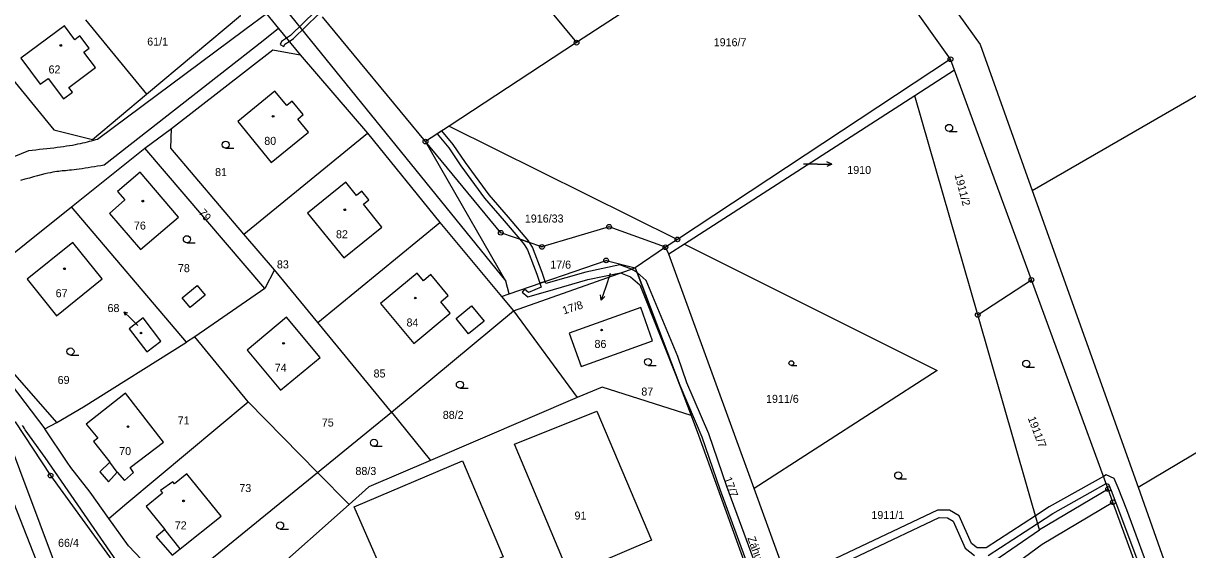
# Model space of a CAD drawing. Extents: x -504988 to -494607, y -1123820 to -1114018.
# Drawn here: x -497559.8 to -497312.5, y -1119487.8 to -1119375.9 of the extents above; entities that cross this region are included whole.
import ezdxf

# ---------------------------------------------------------------- set-up
doc = ezdxf.new("R2010")
doc.units = 0
for name, color, linetype in [('Hranice parcel', 7, 'Continuous'), ('Parcelní čísla', 7, 'Continuous'), ('Pop  PČ popisy', 7, 'Continuous'), ('Vnitřní kresba', 7, 'Continuous'), ('Věcná břemena k části', 7, 'Continuous'), ('Značky bodu BP', 7, 'Continuous'), ('Značky budov', 7, 'Continuous'), ('Značky kultur', 7, 'Continuous')]:
    doc.layers.add(name, color=color, linetype=linetype)

msp = doc.modelspace()

# ---------------------------------------------------------------- linework, layer by layer
at = {"layer": 'Hranice parcel'}
for p, q in [((-497362.83, -1119383.54), (-497389.7, -1119345.59)), ((-497466.94, -1119350.12), (-497442.25, -1119380.02)), ((-497413.46, -1119361.16), (-497442.25, -1119380.02)), ((-497546.51, -1119375.18), (-497533.57, -1119390.95)), ((-497474.33, -1119401.04), (-497496.22, -1119374.52)), ((-497442.25, -1119380.02), (-497469.31, -1119397.75)), ((-497500.92, -1119382.63), (-497486.64, -1119399.22)), ((-497362.83, -1119383.54), (-497420.84, -1119421.83)), ((-497361.97, -1119385.89), (-497362.83, -1119383.54)), ((-497361.97, -1119385.89), (-497370.38, -1119391.3)), ((-497345.64, -1119430.45), (-497361.97, -1119385.89)), ((-497370.38, -1119391.3), (-497419.32, -1119422.82)), ((-497357.03, -1119437.88), (-497370.38, -1119391.3)), ((-497533.91, -1119402.42), (-497528.28, -1119398.23)), ((-497469.31, -1119397.75), (-497474.33, -1119401.04)), ((-497469.31, -1119397.75), (-497420.84, -1119421.83)), ((-497512.89, -1119420.75), (-497486.64, -1119399.22)), ((-497486.64, -1119399.22), (-497471.31, -1119418.26)), ((-497549.48, -1119414.92), (-497533.91, -1119402.42)), ((-497508.44, -1119432.28), (-497533.91, -1119402.42)), ((-497345.47, -1119411.41), (-497322.99, -1119474.49)), ((-497525.07, -1119443.64), (-497549.48, -1119414.92)), ((-497497.21, -1119439.47), (-497471.31, -1119418.26)), ((-497471.31, -1119418.26), (-497458.19, -1119433.94)), ((-497506.41, -1119428.32), (-497512.89, -1119420.75)), ((-497420.84, -1119421.83), (-497423.37, -1119423.49)), ((-497419.32, -1119422.82), (-497422.68, -1119424.99)), ((-497423.37, -1119423.49), (-497429.79, -1119427.85)), ((-497422.68, -1119424.99), (-497423.37, -1119423.49)), ((-497404.54, -1119474.79), (-497422.68, -1119424.99)), ((-497506.41, -1119428.32), (-497508.44, -1119432.28)), ((-497497.21, -1119439.47), (-497506.41, -1119428.32)), ((-497455.62, -1119437.01), (-497429.79, -1119427.85)), ((-497429.79, -1119427.85), (-497417.89, -1119459.27)), ((-497357.03, -1119437.88), (-497345.64, -1119430.45)), ((-497329.36, -1119474.87), (-497345.64, -1119430.45)), ((-497508.44, -1119432.28), (-497523.31, -1119442.55)), ((-497458.19, -1119433.94), (-497456.56, -1119433.38)), ((-497458.19, -1119433.94), (-497455.62, -1119437.01)), ((-497481.58, -1119458.57), (-497455.62, -1119437.01)), ((-497455.62, -1119437.01), (-497442.09, -1119455.42)), ((-497343.95, -1119483.52), (-497357.03, -1119437.88)), ((-497481.58, -1119458.57), (-497497.21, -1119439.47)), ((-497523.31, -1119442.55), (-497525.07, -1119443.64)), ((-497511.96, -1119456.38), (-497523.31, -1119442.55)), ((-497442.09, -1119455.42), (-497473.29, -1119468.81)), ((-497497.24, -1119471.33), (-497511.96, -1119456.38)), ((-497550.62, -1119497.04), (-497564.6, -1119459.85)), ((-497497.24, -1119471.33), (-497481.58, -1119458.57)), ((-497481.58, -1119458.57), (-497473.29, -1119468.81)), ((-497497.24, -1119471.33), (-497490.57, -1119478.17)), ((-497389.87, -1119515.08), (-497404.54, -1119474.79)), ((-497329.36, -1119474.87), (-497343.95, -1119483.52)), ((-497328.33, -1119477.67), (-497329.36, -1119474.87)), ((-497322.99, -1119474.49), (-497308.05, -1119516.41)), ((-497313.08, -1119519.28), (-497328.33, -1119477.67)), ((-497490.57, -1119478.17), (-497517.69, -1119502.28)), ((-497389.87, -1119515.08), (-497343.95, -1119483.52))]:
    msp.add_line(p, q, dxfattribs=at)
for points in [[(-497345.47, -1119411.41), (-497239.07, -1119349.88), (-497099.83, -1119289.69), (-496924.26, -1119247.46), (-496748.68, -1119205.23), (-496605.31, -1119200.3), (-496461.93, -1119195.37), (-496309.61, -1119194.8), (-496157.29, -1119194.24), (-496004.97, -1119193.67), (-495852.65, -1119193.1)], [(-497322.99, -1119474.49), (-497208.3, -1119406.17), (-497084.81, -1119346.13), (-497021.3, -1119330)], [(-497369.23, -1119362.71), (-497356.53, -1119380.38), (-497345.47, -1119411.41)], [(-497533.57, -1119390.95), (-497513.6, -1119374.26), (-497513.05, -1119367.92)], [(-497513.05, -1119367.92), (-497508.11, -1119373.91), (-497505.55, -1119377.01), (-497500.92, -1119382.63)], [(-497574.81, -1119372.28), (-497553.27, -1119398.56), (-497545.07, -1119400.57), (-497533.57, -1119390.95)], [(-497546.88, -1119382.01), (-497545.79, -1119381.2), (-497547.74, -1119378.59), (-497548.81, -1119379.39), (-497551.01, -1119376.44), (-497560.28, -1119383.34), (-497556.16, -1119388.87), (-497554.47, -1119387.61), (-497551.23, -1119391.96), (-497549.33, -1119390.54), (-497550.08, -1119389.54), (-497544.42, -1119385.33), (-497546.88, -1119382.01)], [(-497528.28, -1119398.23), (-497506.74, -1119381.55), (-497500.92, -1119382.63)], [(-497506.3, -1119390.33), (-497514.19, -1119396.79), (-497507.09, -1119405.47), (-497499.19, -1119399.01), (-497501.45, -1119396.25), (-497500.32, -1119395.32), (-497502.67, -1119392.46), (-497503.8, -1119393.39), (-497506.3, -1119390.33)], [(-497534.22, -1119818.76), (-497527.7, -1119797.51), (-497526.57, -1119794.64), (-497519.56, -1119770.79), (-497516.99, -1119756.52), (-497516.74, -1119750.54), (-497517.29, -1119646.04), (-497517.49, -1119635.34), (-497517.68, -1119614.14), (-497518.78, -1119606.17), (-497521.17, -1119596.67), (-497524.36, -1119587.14), (-497528.66, -1119575.06), (-497536.08, -1119553.14), (-497545.22, -1119526.23), (-497548.05, -1119512.85), (-497563.82, -1119472.59), (-497575.6, -1119448.97), (-497587.45, -1119432.22), (-497598.97, -1119413.96), (-497613.75, -1119397.19), (-497616.09, -1119394)], [(-497512.89, -1119420.75), (-497528.45, -1119402.46), (-497528.28, -1119398.23)], [(-497456.56, -1119433.38), (-497457.24, -1119430.73), (-497474.33, -1119401.04)], [(-497423.37, -1119423.49), (-497435.33, -1119419.15), (-497449.59, -1119423.42), (-497458.34, -1119420.41), (-497474.33, -1119401.04)], [(-497538.16, -1119413.45), (-497541.47, -1119416.29), (-497534.85, -1119424), (-497526.77, -1119417.07), (-497534.95, -1119407.53), (-497539.72, -1119411.62), (-497538.16, -1119413.45)], [(-497487.5, -1119414.36), (-497486.33, -1119413.42), (-497487.82, -1119411.56), (-497488.99, -1119412.5), (-497491.25, -1119409.7), (-497499.36, -1119416.24), (-497491.68, -1119425.76), (-497483.58, -1119419.22), (-497487.5, -1119414.36)], [(-497552.64, -1119460.76), (-497562.49, -1119449.45), (-497568.85, -1119430.36), (-497549.48, -1119414.92)], [(-497543.03, -1119430.24), (-497549.26, -1119422.5), (-497558.96, -1119430.29), (-497552.73, -1119438.04), (-497543.03, -1119430.24)], [(-497419.32, -1119422.82), (-497365.69, -1119449.72), (-497404.54, -1119474.79)], [(-497456.56, -1119433.38), (-497435.97, -1119426.3), (-497429.79, -1119427.85)], [(-497483.91, -1119435.44), (-497476.84, -1119443.98), (-497469.07, -1119437.53), (-497471.1, -1119435.08), (-497469.52, -1119433.77), (-497473.21, -1119429.32), (-497474.79, -1119430.63), (-497476.13, -1119429), (-497483.91, -1119435.44)], [(-497428.6, -1119436.29), (-497443.8, -1119441.73), (-497441.28, -1119448.83), (-497426.1, -1119443.4), (-497428.6, -1119436.29)], [(-497530.51, -1119443.42), (-497534.29, -1119438.5), (-497537.28, -1119440.8), (-497533.5, -1119445.72), (-497530.51, -1119443.42)], [(-497496.71, -1119446.91), (-497503.84, -1119438.35), (-497512.24, -1119445.34), (-497505.11, -1119453.9), (-497496.71, -1119446.91)], [(-497552.64, -1119460.76), (-497546.99, -1119457.42), (-497525.07, -1119443.64)], [(-497543.93, -1119464.1), (-497544.85, -1119464.8), (-497541.38, -1119469.14), (-497543.52, -1119471.25), (-497541.68, -1119473.36), (-497539.78, -1119471.29), (-497538.25, -1119473.05), (-497536.34, -1119471.36), (-497537.06, -1119470.31), (-497529.97, -1119464.92), (-497538.07, -1119454.52), (-497546.38, -1119461.07), (-497543.93, -1119464.1)], [(-497417.89, -1119459.27), (-497436.82, -1119453.23), (-497442.09, -1119455.42)], [(-497541.59, -1119481.12), (-497537.74, -1119477.89), (-497511.96, -1119456.38)], [(-497564.6, -1119459.85), (-497561.45, -1119460.61), (-497553.96, -1119472.01), (-497537.91, -1119494.15)], [(-497443.72, -1119493.19), (-497455.45, -1119465.37), (-497437.92, -1119458.34), (-497426.32, -1119485.74), (-497443.72, -1119493.19)], [(-497417.89, -1119459.27), (-497416.38, -1119463.46), (-497396.14, -1119519.39)], [(-497541.59, -1119481.12), (-497545.58, -1119475.53), (-497549.64, -1119470.28), (-497550.46, -1119469.18), (-497555.15, -1119462.06), (-497552.64, -1119460.76)], [(-497473.29, -1119468.81), (-497486.35, -1119474.42), (-497490.57, -1119478.17)], [(-497457.83, -1119489.28), (-497480.66, -1119498.89), (-497489.46, -1119478.67), (-497466.44, -1119468.85), (-497457.83, -1119489.28)], [(-497527.65, -1119473.75), (-497527.96, -1119473.32), (-497530.6, -1119475.22), (-497530.21, -1119475.77), (-497533.64, -1119478.61), (-497529.7, -1119483.5), (-497531.53, -1119485.04), (-497528.11, -1119488.96), (-497526.4, -1119487.58), (-497517.76, -1119480.61), (-497525.01, -1119471.64), (-497527.65, -1119473.75)], [(-497528.16, -1119496.79), (-497524.29, -1119493.36), (-497497.24, -1119471.33)], [(-497352.23, -1119493.11), (-497343.35, -1119486.6), (-497328.33, -1119477.67)], [(-497532.33, -1119492.88), (-497533.3, -1119491.28), (-497537.41, -1119486.97), (-497541.59, -1119481.12)]]:
    msp.add_lwpolyline(points, dxfattribs=at)
at = {"layer": 'Pop  PČ popisy'}
for p, q in [((-497391.06, -1119405.85), (-497394.06, -1119405.85)), ((-497391.06, -1119405.85), (-497388.06, -1119405.85)), ((-497388.06, -1119405.85), (-497389.06, -1119405.35)), ((-497388.06, -1119405.85), (-497389.06, -1119406.35)), ((-497435.08, -1119429.06), (-497436.04, -1119431.89)), ((-497436.04, -1119431.89), (-497437.02, -1119434.73)), ((-497437.02, -1119434.73), (-497437.16, -1119433.62)), ((-497437.02, -1119434.73), (-497436.22, -1119433.94)), ((-497536.91, -1119438.67), (-497538.4, -1119437.19)), ((-497538.4, -1119437.19), (-497537.65, -1119437.43)), ((-497538.4, -1119437.19), (-497538.15, -1119437.93)), ((-497535.43, -1119440.16), (-497536.91, -1119438.67))]:
    msp.add_line(p, q, dxfattribs=at)
at = {"layer": 'Vnitřní kresba'}
for p, q in [((-497545.39, -1119321.91), (-497457.24, -1119430.73)), ((-497508.11, -1119373.91), (-497512.71, -1119377.33)), ((-497512.71, -1119377.33), (-497543.99, -1119400.57)), ((-497505.55, -1119377.01), (-497508.79, -1119379.63)), ((-497508.79, -1119379.63), (-497542.57, -1119406.08)), ((-497558.65, -1119403), (-497566.37, -1119406.14)), ((-497526.01, -1119434.27), (-497522.85, -1119431.64)), ((-497522.85, -1119431.64), (-497521.16, -1119433.67)), ((-497524.32, -1119436.3), (-497526.01, -1119434.27)), ((-497521.16, -1119433.67), (-497524.32, -1119436.3)), ((-497467.84, -1119438.64), (-497464.56, -1119435.93)), ((-497464.56, -1119435.93), (-497461.86, -1119439.19)), ((-497465.23, -1119441.9), (-497467.84, -1119438.64)), ((-497461.86, -1119439.19), (-497465.23, -1119441.9)), ((-497565.57, -1119448.47), (-497555.15, -1119462.06)), ((-497555.12, -1119468.14), (-497559.33, -1119462.27)), ((-497537.26, -1119494), (-497555.12, -1119468.14)), ((-497539.78, -1119471.29), (-497541.38, -1119469.14)), ((-497526.4, -1119487.58), (-497529.7, -1119483.5))]:
    msp.add_line(p, q, dxfattribs=at)
for points in [[(-497543.99, -1119400.57), (-497544.42, -1119400.69), (-497544.87, -1119400.81), (-497545.31, -1119400.93), (-497545.76, -1119401.05), (-497546.22, -1119401.17), (-497546.69, -1119401.28), (-497547.18, -1119401.4), (-497547.69, -1119401.51), (-497548.21, -1119401.62), (-497548.75, -1119401.73), (-497549.33, -1119401.84), (-497549.92, -1119401.94), (-497550.54, -1119402.04), (-497551.2, -1119402.14), (-497551.87, -1119402.23), (-497552.57, -1119402.32), (-497553.29, -1119402.41), (-497554.02, -1119402.5), (-497554.77, -1119402.58), (-497555.54, -1119402.67), (-497556.3, -1119402.75), (-497557.08, -1119402.84), (-497557.87, -1119402.92), (-497558.65, -1119403)], [(-497542.57, -1119406.08), (-497543.27, -1119406.19), (-497543.97, -1119406.3), (-497544.65, -1119406.41), (-497545.33, -1119406.51), (-497545.99, -1119406.61), (-497546.64, -1119406.71), (-497547.26, -1119406.8), (-497547.86, -1119406.89), (-497548.43, -1119406.97), (-497548.97, -1119407.03), (-497549.48, -1119407.1), (-497549.94, -1119407.15), (-497550.36, -1119407.19), (-497550.76, -1119407.23), (-497551.13, -1119407.26), (-497551.49, -1119407.29), (-497551.85, -1119407.33), (-497552.22, -1119407.37), (-497552.6, -1119407.42), (-497553.03, -1119407.48), (-497553.48, -1119407.56), (-497553.99, -1119407.66), (-497554.57, -1119407.78), (-497555.21, -1119407.93), (-497555.93, -1119408.11), (-497556.73, -1119408.31), (-497557.57, -1119408.54), (-497558.46, -1119408.79), (-497559.4, -1119409.06), (-497560.34, -1119409.34)], [(-497559.33, -1119462.27), (-497559.52, -1119461.98), (-497559.71, -1119461.69), (-497559.9, -1119461.41)]]:
    msp.add_lwpolyline(points, dxfattribs=at)
at = {"layer": 'Věcná břemena k části'}
for points in [[(-497497.39, -1119373.11), (-497497.71, -1119373.36), (-497503.01, -1119378.47), (-497503.87, -1119379.05), (-497504.91, -1119379.76), (-497505.23, -1119380.44), (-497504.41, -1119380.82), (-497504.18, -1119380.34), (-497503.3, -1119379.74), (-497502.39, -1119379.13), (-497497.12, -1119374.03), (-497496.82, -1119373.8)], [(-497468.45, -1119401.66), (-497470.83, -1119398.75), (-497471.84, -1119399.41), (-497469.41, -1119402.38), (-497466.85, -1119406.19), (-497461.77, -1119413.09), (-497457.62, -1119417.87), (-497454.33, -1119421.79), (-497452.22, -1119422.52), (-497452.41, -1119422.21), (-497456.7, -1119417.09), (-497460.83, -1119412.33), (-497465.87, -1119405.49)], [(-497454.33, -1119421.79), (-497453.39, -1119422.91), (-497452.68, -1119424.05), (-497450.72, -1119429.24), (-497450.08, -1119431.15), (-497448.94, -1119430.76), (-497449.58, -1119428.84), (-497451.6, -1119423.51), (-497452.22, -1119422.52)], [(-497450.08, -1119431.15), (-497449.79, -1119432), (-497452.49, -1119433.11), (-497453.31, -1119432.42), (-497453.82, -1119433.03), (-497452.63, -1119434.03), (-497448.84, -1119432.94), (-497439.86, -1119430.38), (-497432.92, -1119428.96), (-497430.79, -1119429.78), (-497428.78, -1119431.51), (-497420.34, -1119452.79), (-497429.41, -1119428.84), (-497430.6, -1119428.14), (-497433.04, -1119427.21), (-497440.26, -1119428.82), (-497448.79, -1119431.23), (-497448.94, -1119430.76)]]:
    msp.add_lwpolyline(points, close=True, dxfattribs=at)
for points in [[(-497402.48, -1119495.69), (-497410.31, -1119474.35), (-497414.14, -1119463.17), (-497418.81, -1119452.3), (-497420.71, -1119446.7), (-497427.44, -1119430.55), (-497429.41, -1119428.84), (-497420.34, -1119452.79), (-497415.64, -1119463.75), (-497411.81, -1119474.89), (-497403.93, -1119496.39)], [(-497319.64, -1119494.85), (-497325.41, -1119479.33), (-497327.21, -1119474.6), (-497328.04, -1119472.65), (-497329.79, -1119471.89), (-497330.34, -1119472.2), (-497341.89, -1119478.67), (-497344.8, -1119480.56), (-497355.28, -1119487.37), (-497357.2, -1119487.37), (-497358.39, -1119486.45), (-497360.97, -1119480.59), (-497363.05, -1119479.4), (-497365.57, -1119479.35), (-497396.79, -1119494.14)], [(-497354.8, -1119488.97), (-497344.34, -1119482.17), (-497341.07, -1119480.05), (-497329.78, -1119473.72), (-497329.26, -1119473.87), (-497328.69, -1119475.2), (-497326.91, -1119479.89), (-497321.14, -1119495.41)], [(-497396.23, -1119495.64), (-497365.23, -1119480.95), (-497363.49, -1119481), (-497362.23, -1119481.71), (-497359.69, -1119487.47), (-497357.74, -1119488.97)]]:
    msp.add_lwpolyline(points, dxfattribs=at)
at = {"layer": 'Značky bodu BP'}
for centre, radius in [((-497442.25, -1119380.02), 0.5), ((-497442.25, -1119380.02), 0.0303), ((-497362.83, -1119383.54), 0.5), ((-497362.83, -1119383.54), 0.0303), ((-497474.33, -1119401.04), 0.5), ((-497474.33, -1119401.04), 0.0303), ((-497458.34, -1119420.41), 0.5), ((-497458.34, -1119420.41), 0.0303), ((-497435.33, -1119419.15), 0.5), ((-497435.33, -1119419.15), 0.0303), ((-497449.59, -1119423.42), 0.5), ((-497449.59, -1119423.42), 0.0303), ((-497423.37, -1119423.49), 0.5), ((-497420.84, -1119421.83), 0.5), ((-497420.84, -1119421.83), 0.0303), ((-497435.97, -1119426.3), 0.5), ((-497423.37, -1119423.49), 0.0303), ((-497435.97, -1119426.3), 0.0303), ((-497345.64, -1119430.45), 0.5), ((-497345.64, -1119430.45), 0.0303), ((-497357.03, -1119437.88), 0.5), ((-497357.03, -1119437.88), 0.0303), ((-497553.96, -1119472.01), 0.5), ((-497553.96, -1119472.01), 0.0303), ((-497329.36, -1119474.87), 0.5), ((-497329.36, -1119474.87), 0.0303), ((-497328.33, -1119477.67), 0.5), ((-497328.33, -1119477.67), 0.0303)]:
    msp.add_circle(centre, radius, dxfattribs=at)
at = {"layer": 'Značky budov'}
for centre in [(-497551.79, -1119380.61), (-497506.7, -1119395.69), (-497534.38, -1119413.69), (-497491.47, -1119415.53), (-497551.01, -1119428.07), (-497476.49, -1119434.29), (-497534.76, -1119441.72), (-497436.93, -1119441.09), (-497504.48, -1119443.92), (-497537.52, -1119461.61), (-497525.71, -1119477.4)]:
    msp.add_circle(centre, 0.175, dxfattribs=at)
at = {"layer": 'Značky kultur'}
for p, q in [((-497363.13, -1119398.88), (-497361.38, -1119398.88)), ((-497516.78, -1119402.45), (-497515.03, -1119402.45)), ((-497525.01, -1119422.54), (-497523.26, -1119422.54)), ((-497549.73, -1119446.4), (-497547.98, -1119446.4)), ((-497427.06, -1119448.62), (-497425.31, -1119448.62)), ((-497396.62, -1119448.62), (-497395.45, -1119448.62)), ((-497346.75, -1119449), (-497345, -1119449)), ((-497467.03, -1119453.45), (-497465.28, -1119453.45)), ((-497485.27, -1119465.79), (-497483.52, -1119465.79)), ((-497373.93, -1119472.74), (-497372.18, -1119472.74)), ((-497505.21, -1119483.37), (-497503.46, -1119483.37))]:
    msp.add_line(p, q, dxfattribs=at)
for centre, radius in [((-497363.13, -1119398.13), 0.75), ((-497516.78, -1119401.7), 0.75), ((-497525.01, -1119421.79), 0.75), ((-497549.73, -1119445.65), 0.75), ((-497427.06, -1119447.87), 0.75), ((-497396.63, -1119448.12), 0.502), ((-497346.75, -1119448.25), 0.75), ((-497467.03, -1119452.7), 0.75), ((-497485.27, -1119465.04), 0.75), ((-497373.93, -1119471.99), 0.75), ((-497505.21, -1119482.62), 0.75)]:
    msp.add_circle(centre, radius, dxfattribs=at)

# ---------------------------------------------------------------- texts
at = {"layer": 'Parcelní čísla'}
for s, p in [('61/1', (-497533.43, -1119380.64)), ('1916/7', (-497413.12, -1119380.78)), ('62', (-497554.39, -1119386.56)), ('80', (-497508.57, -1119401.74)), ('81', (-497519.02, -1119408.37)), ('1910', (-497384.75, -1119407.92)), ('76', (-497536.25, -1119419.74)), ('1916/33', (-497453.23, -1119418.24)), ('82', (-497493.34, -1119421.58)), ('78', (-497526.91, -1119428.79)), ('83', (-497505.89, -1119427.99)), ('17/6', (-497447.84, -1119428.04)), ('67', (-497552.88, -1119434.12)), ('68', (-497541.86, -1119437.27)), ('84', (-497478.36, -1119440.34)), ('86', (-497438.44, -1119444.89)), ('74', (-497506.35, -1119449.97)), ('85', (-497485.36, -1119451.17)), ('69', (-497552.46, -1119452.55)), ('87', (-497428.49, -1119455.01)), ('1911/6', (-497402.01, -1119456.56)), ('71', (-497526.97, -1119461.14)), ('75', (-497496.35, -1119461.59)), ('88/2', (-497470.66, -1119459.97)), ('70', (-497539.39, -1119467.66)), ('88/3', (-497489.21, -1119471.89)), ('73', (-497513.87, -1119475.52)), ('91', (-497442.68, -1119481.36)), ('1911/1', (-497379.63, -1119481.25)), ('72', (-497527.58, -1119483.45)), ('66/4', (-497552.37, -1119487.16))]:
    msp.add_text(s, height=1.7, dxfattribs=at).set_placement(p)
for s, rotation, p in [('1911/2', 285, (-497361.98, -1119408.16)), ('79', 310, (-497522.63, -1119416.2)), ('17/8', 18, (-497444.94, -1119437.8)), ('1911/7', 291, (-497346.45, -1119459.81)), ('17/7', 290, (-497410.99, -1119472.64))]:
    msp.add_text(s, height=1.7, rotation=rotation, dxfattribs=at).set_placement(p)
at = {"layer": 'Pop  PČ popisy'}
msp.add_text('Záhumení', height=1.7, rotation=290, dxfattribs=at).set_placement((-497405.98, -1119485.29))

doc.saveas('drawing.dxf')
